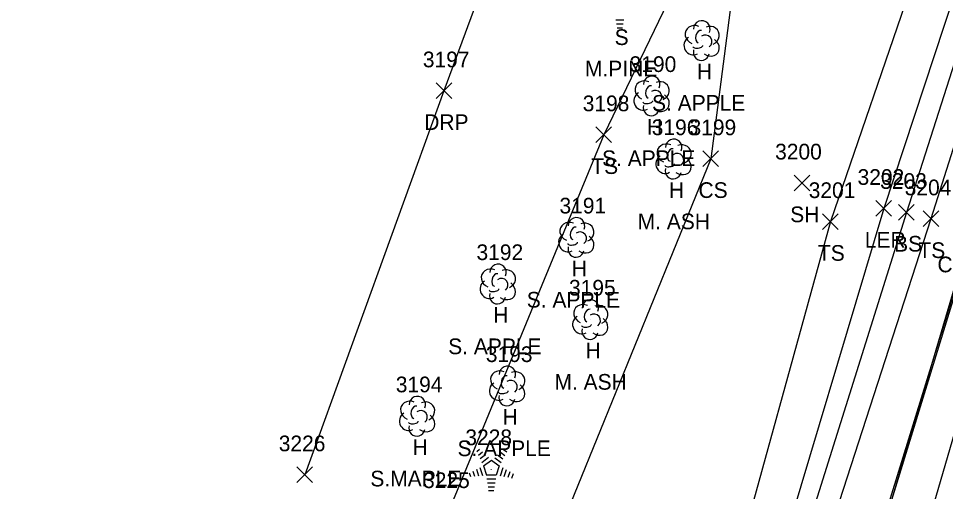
# Model space of a CAD drawing. Extents: x 1462089 to 1464015, y 730534 to 736144.
# Drawn here: x 1462931.1 to 1463049.3, y 732967.5 to 733027.8 of the extents above; entities that cross this region are included whole.
import ezdxf

# ---------------------------------------------------------------- set-up
doc = ezdxf.new("R2010")
doc.units = 0
for name, color, linetype in [('DCP', 7, 'Continuous'), ('L_A', 7, 'Continuous'), ('L_C', 7, 'Continuous'), ('L_I', 7, 'Continuous'), ('L_TIC', 7, 'Continuous'), ('LARO', 7, 'Continuous'), ('LELB', 7, 'Continuous'), ('LTC', 7, 'Continuous'), ('LTD', 7, 'Continuous'), ('PET', 7, 'Continuous'), ('PSP', 7, 'Continuous'), ('R_A', 7, 'Continuous'), ('R_I', 7, 'Continuous'), ('R_TIC', 7, 'Continuous'), ('RC', 7, 'Continuous'), ('RDP', 7, 'Continuous')]:
    doc.layers.add(name, color=color, linetype=linetype)

msp = doc.modelspace()

# ---------------------------------------------------------------- linework, layer by layer
at = {"layer": 'DCP'}
msp.add_lwpolyline([(1463113.91, 733208.21), (1463020.77, 732893.28)], dxfattribs=at)
at = {"layer": 'L_TIC'}
for points in [[(1463004.74, 733012.02), (1463006.74, 733014.02)], [(1463006.74, 733012.02), (1463004.74, 733014.02)], [(1463018.37, 733008.96), (1463020.37, 733010.96)], [(1463020.37, 733008.96), (1463018.37, 733010.96)], [(1463030.01, 733005.87), (1463032.01, 733007.87)], [(1463032.01, 733005.87), (1463030.01, 733007.87)], [(1463040.43, 733002.63), (1463042.43, 733004.63)], [(1463042.43, 733002.63), (1463040.43, 733004.63)], [(1463043.31, 733002.12), (1463045.31, 733004.12)], [(1463045.31, 733002.12), (1463043.31, 733004.12)], [(1463033.63, 733000.95), (1463035.63, 733002.95)], [(1463035.63, 733000.95), (1463033.63, 733002.95)], [(1463046.44, 733001.3), (1463048.44, 733003.3)], [(1463048.44, 733001.3), (1463046.44, 733003.3)]]:
    msp.add_lwpolyline(points, dxfattribs=at)
at = {"layer": 'LARO'}
msp.add_lwpolyline([(1463094.76, 733228.15), (1463096.03, 733229.51), (1463107.11, 733225.67), (1463106.44, 733220.79), (1463101.84, 733210.57), (1463094.26, 733183.58), (1463093.23, 733172.66), (1463084.96, 733140.71), (1463082.5, 733130.85), (1463075.1, 733107.4), (1463060.71, 733062.18), (1463041.43, 733003.63), (1463027.29, 732956.25), (1463020.7, 732939.68), (1463009.72, 732922.59), (1463000.8, 732913.83)], dxfattribs=at)
at = {"layer": 'LELB'}
for points in [[(1463108.71, 733226.1), (1463108.78, 733215.45), (1463107.91, 733210.67), (1463106.52, 733207.37), (1463097.65, 733182.34), (1463096.33, 733171.82), (1463062.97, 733061.46), (1463044.31, 733003.12), (1463029.33, 732955.28), (1463018.11, 732921.02), (1463012.52, 732895.45), (1463002.14, 732868.56), (1462989.94, 732828.37), (1462974.14, 732778.17), (1462962.05, 732738.86), (1462942.09, 732684.7)], [(1463108.71, 733226.1), (1463110.44, 733215.45), (1463109.61, 733208.14), (1463106.26, 733200.46), (1463099.08, 733171.5), (1463080.2, 733104.81), (1463066.07, 733061.12), (1463047.44, 733002.3), (1463031.89, 732954.26), (1463021.29, 732920.45), (1463016.04, 732893.81), (1463006.16, 732867.27), (1462993.39, 732826.96), (1462975.9, 732776.47), (1462964.59, 732738.3), (1462945.3, 732683.44)], [(1463035.34, 733085.44), (1463029.83, 733068.95), (1463024.96, 733052.89), (1463005.74, 733013.02), (1462985.96, 732964.97), (1462972.93, 732929.05)], [(1463055.63, 733063.21), (1463034.63, 733001.95), (1463021.17, 732953.09), (1463005.86, 732923.5), (1463000.8, 732913.83), (1462995.2, 732902.16), (1462991.68, 732870.51), (1462983.42, 732830.89), (1462971.91, 732797.99), (1462967.45, 732788.36), (1462962, 732775.43), (1462963.84, 732771.36), (1462954.15, 732748.13), (1462943.9, 732732.26), (1462943.46, 732721.31), (1462938.53, 732701.15), (1462919.19, 732660.62)], [(1463024.96, 733052.89), (1463019.37, 733009.96), (1463000.01, 732962.33), (1462984.86, 732926.01), (1462972.76, 732908.94), (1462960.37, 732884.47), (1462958.09, 732841.86), (1462948.33, 732829.18), (1462951.8, 732798.65), (1462940.09, 732777.68), (1462936.2, 732747.89), (1462927.88, 732723.49), (1462921.5, 732707.29), (1462904.86, 732665.94), (1462895.56, 732628.88), (1462895.22, 732616.02)]]:
    msp.add_lwpolyline(points, dxfattribs=at)
at = {"layer": 'LTC'}
for p, q in [((1463008.28, 733027.62), (1463007.29, 733027.62)), ((1463008.19, 733027.12), (1463007.36, 733027.12)), ((1463008.11, 733026.62), (1463007.43, 733026.62)), ((1462989.55, 732972.65), (1462989.9, 732972.91)), ((1462989.76, 732972.18), (1462990.29, 732972.57)), ((1462989.97, 732971.72), (1462990.67, 732972.23)), ((1462990.18, 732971.25), (1462991.05, 732971.89)), ((1462991.83, 732971.84), (1462992.64, 732971.25)), ((1462992.2, 732972.19), (1462992.88, 732971.7)), ((1462992.57, 732972.54), (1462993.12, 732972.14)), ((1462992.95, 732972.89), (1462993.37, 732972.58)), ((1462989.95, 732970.58), (1462990.28, 732969.56)), ((1462990.4, 732970.8), (1462991.41, 732971.53)), ((1462990.4, 732970.8), (1462990.79, 732969.6)), ((1462991.41, 732971.53), (1462992.41, 732970.81)), ((1462992.41, 732970.81), (1462992.02, 732969.6)), ((1462988.58, 732969.93), (1462988.73, 732969.46)), ((1462989.04, 732970.14), (1462989.25, 732969.49)), ((1462989.49, 732970.36), (1462989.76, 732969.53)), ((1462992.02, 732969.6), (1462990.79, 732969.6)), ((1462992.85, 732970.53), (1462992.51, 732969.5)), ((1462993.29, 732970.28), (1462993, 732969.4)), ((1462993.74, 732970.03), (1462993.5, 732969.3)), ((1462994.18, 732969.78), (1462993.99, 732969.21)), ((1462991.98, 732969.1), (1462990.84, 732969.1)), ((1462991.9, 732968.6), (1462990.91, 732968.6)), ((1462991.81, 732968.1), (1462990.98, 732968.1)), ((1462991.73, 732967.6), (1462991.05, 732967.6))]:
    msp.add_line(p, q, dxfattribs=at)
at = {"layer": 'LTD'}
for p, q in [((1463018.19, 733025.08), (1463018.19, 733025.08)), ((1463018.19, 733025.08), (1463018.19, 733025.08)), ((1463011.81, 733018.02), (1463011.81, 733018.02)), ((1463011.81, 733018.02), (1463011.81, 733018.02)), ((1463014.6, 733009.97), (1463014.6, 733009.97)), ((1463014.6, 733009.97), (1463014.6, 733009.97)), ((1463002.21, 732999.98), (1463002.21, 732999.98)), ((1463002.21, 732999.98), (1463002.21, 732999.98)), ((1462992.2, 732994.04), (1462992.2, 732994.04)), ((1462992.2, 732994.04), (1462992.2, 732994.04)), ((1463003.99, 732989.51), (1463003.99, 732989.51)), ((1463003.99, 732989.51), (1463003.99, 732989.51)), ((1462993.39, 732981.04), (1462993.39, 732981.04)), ((1462993.39, 732981.04), (1462993.39, 732981.04)), ((1462981.92, 732977.18), (1462981.92, 732977.18)), ((1462981.92, 732977.18), (1462981.92, 732977.18))]:
    msp.add_line(p, q, dxfattribs=at)
for centre in [(1463018.24, 733026.51), (1463011.86, 733019.45), (1463014.65, 733011.41), (1463002.26, 733001.41), (1462992.25, 732995.47), (1463004.04, 732990.94), (1462993.44, 732982.47), (1462981.96, 732978.62)]:
    msp.add_arc(centre, 1.05, 335.5272, 180.9563, dxfattribs=at)
for centre, major_axis, ratio, start_param, end_param in [((1463017.4, 733025.75), (1.21, -0.51), 0.895232, 1.570796, 4.712389), ((1463017.98, 733025.54), (-0.208, -0.792), 0.645439, 3.141593, 6.283185), ((1463019.23, 733025.66), (-1.14, -0.48), 0.949671, 1.570796, 4.712389), ((1463017.11, 733024.37), (0.58, -1.04), 0.959034, 3.141593, 6.283185), ((1463018.69, 733024.91), (-0.5, 0.667), 0.989748, 3.141593, 6.283185), ((1463019.19, 733024.25), (-1.09, 0.79), 0.841452, 1.570796, 4.712389), ((1463018.19, 733023.58), (0.26, 1.06), 0.942809, 1.570796, 4.712389), ((1463017.73, 733024.33), (-0.625, -0.083), 0.423636, 0, 3.141593), ((1463011.02, 733018.69), (1.21, -0.51), 0.895232, 1.570796, 4.712389), ((1463011.61, 733018.48), (-0.208, -0.792), 0.645439, 3.141593, 6.283185), ((1463012.86, 733018.6), (-1.14, -0.48), 0.949671, 1.570796, 4.712389), ((1463010.73, 733017.31), (0.58, -1.04), 0.959034, 3.141593, 6.283185), ((1463012.31, 733017.85), (-0.5, 0.667), 0.989748, 3.141593, 6.283185), ((1463012.81, 733017.19), (-1.09, 0.79), 0.841452, 1.570796, 4.712389), ((1463011.81, 733016.52), (0.26, 1.06), 0.942809, 1.570796, 4.712389), ((1463011.36, 733017.27), (-0.625, -0.083), 0.423636, 0, 3.141593), ((1463013.81, 733010.64), (1.21, -0.51), 0.895232, 1.570796, 4.712389), ((1463014.39, 733010.43), (-0.208, -0.792), 0.645439, 3.141593, 6.283185), ((1463015.64, 733010.56), (-1.14, -0.48), 0.949671, 1.570796, 4.712389), ((1463013.52, 733009.27), (0.58, -1.04), 0.959034, 3.141593, 6.283185), ((1463015.1, 733009.81), (-0.5, 0.667), 0.989748, 3.141593, 6.283185), ((1463015.6, 733009.14), (-1.09, 0.79), 0.841452, 1.570796, 4.712389), ((1463014.6, 733008.47), (0.26, 1.06), 0.942809, 1.570796, 4.712389), ((1463014.14, 733009.22), (-0.625, -0.083), 0.423636, 0, 3.141593), ((1463001.42, 733000.65), (1.21, -0.51), 0.895232, 1.570796, 4.712389), ((1463002.01, 733000.44), (-0.208, -0.792), 0.645439, 3.141593, 6.283185), ((1463003.26, 733000.56), (-1.14, -0.48), 0.949671, 1.570796, 4.712389), ((1463001.13, 732999.27), (0.58, -1.04), 0.959034, 3.141593, 6.283185), ((1463002.71, 732999.81), (-0.5, 0.667), 0.989748, 3.141593, 6.283185), ((1463001.76, 732999.23), (-0.625, -0.083), 0.423636, 0, 3.141593), ((1463003.21, 732999.15), (-1.09, 0.79), 0.841452, 1.570796, 4.712389), ((1463002.21, 732998.48), (0.26, 1.06), 0.942809, 1.570796, 4.712389), ((1462991.41, 732994.7), (1.21, -0.51), 0.895232, 1.570796, 4.712389), ((1462993.25, 732994.62), (-1.14, -0.48), 0.949671, 1.570796, 4.712389), ((1462991.12, 732993.33), (0.58, -1.04), 0.959034, 3.141593, 6.283185), ((1462992, 732994.49), (-0.208, -0.792), 0.645439, 3.141593, 6.283185), ((1462992.7, 732993.87), (-0.5, 0.667), 0.989748, 3.141593, 6.283185), ((1462991.75, 732993.29), (-0.625, -0.083), 0.423636, 0, 3.141593), ((1462993.2, 732993.2), (-1.09, 0.79), 0.841452, 1.570796, 4.712389), ((1462992.2, 732992.54), (0.26, 1.06), 0.942809, 1.570796, 4.712389), ((1463003.2, 732990.17), (1.21, -0.51), 0.895232, 1.570796, 4.712389), ((1463003.78, 732989.97), (-0.208, -0.792), 0.645439, 3.141593, 6.283185), ((1463005.03, 732990.09), (-1.14, -0.48), 0.949671, 1.570796, 4.712389), ((1463002.91, 732988.8), (0.58, -1.04), 0.959034, 3.141593, 6.283185), ((1463004.49, 732989.34), (-0.5, 0.667), 0.989748, 3.141593, 6.283185), ((1463004.99, 732988.67), (-1.09, 0.79), 0.841452, 1.570796, 4.712389), ((1463003.53, 732988.76), (-0.625, -0.083), 0.423636, 0, 3.141593), ((1463003.99, 732988.01), (0.26, 1.06), 0.942809, 1.570796, 4.712389), ((1462992.6, 732981.71), (1.21, -0.51), 0.895232, 1.570796, 4.712389), ((1462994.44, 732981.62), (-1.14, -0.48), 0.949671, 1.570796, 4.712389), ((1462992.31, 732980.33), (0.58, -1.04), 0.959034, 3.141593, 6.283185), ((1462993.19, 732981.5), (-0.208, -0.792), 0.645439, 3.141593, 6.283185), ((1462993.89, 732980.87), (-0.5, 0.667), 0.989748, 3.141593, 6.283185), ((1462992.94, 732980.29), (-0.625, -0.083), 0.423636, 0, 3.141593), ((1462994.39, 732980.21), (-1.09, 0.79), 0.841452, 1.570796, 4.712389), ((1462981.12, 732977.85), (1.21, -0.51), 0.895232, 1.570796, 4.712389), ((1462982.96, 732977.77), (-1.14, -0.48), 0.949671, 1.570796, 4.712389), ((1462993.39, 732979.54), (0.26, 1.06), 0.942809, 1.570796, 4.712389), ((1462981.71, 732977.64), (-0.208, -0.792), 0.645439, 3.141593, 6.283185), ((1462982.42, 732977.02), (-0.5, 0.667), 0.989748, 3.141593, 6.283185), ((1462980.83, 732976.47), (0.58, -1.04), 0.959034, 3.141593, 6.283185), ((1462981.46, 732976.43), (-0.625, -0.083), 0.423636, 0, 3.141593), ((1462982.92, 732976.35), (-1.09, 0.79), 0.841452, 1.570796, 4.712389), ((1462981.92, 732975.68), (0.26, 1.06), 0.942809, 1.570796, 4.712389)]:
    msp.add_ellipse(centre, major_axis=major_axis, ratio=ratio, start_param=start_param, end_param=end_param, dxfattribs=at)
at = {"layer": 'PET'}
msp.add_lwpolyline([(1463162.64, 733438.25), (1463155.29, 733389.19), (1463147.91, 733342.63), (1463141.51, 733306.47), (1463132.06, 733260.3), (1463123.36, 733223.56), (1463108.71, 733168.54), (1463089.87, 733101.56), (1463076.27, 733055.88), (1463056.85, 732997.04), (1463043.72, 732952), (1463030.35, 732910.94), (1463015.8, 732864.49), (1463002.53, 732823.32), (1462986.53, 732773.32), (1462974.36, 732735), (1462957.21, 732680.82)], dxfattribs=at)
at = {"layer": 'PSP'}
msp.add_lwpolyline([(1463155.47, 733437.1), (1463151.69, 733409.08), (1463149, 733391.93), (1463141.96, 733349.08), (1463135.18, 733308.49), (1463125.93, 733264.09), (1463122.72, 733251.49), (1463119.11, 733234.45), (1463113.24, 733211.25), (1463103.08, 733170.52), (1463084.78, 733103.69), (1463070.66, 733057.94), (1463052.86, 733000.45), (1463038.28, 732952.98), (1463025.31, 732912.14), (1463010.74, 732866.35), (1462997.43, 732825.46), (1462981.2, 732774.91), (1462968.73, 732736.5), (1462951.61, 732681.88)], dxfattribs=at)
at = {"layer": 'R_TIC'}
for points in [[(1462984.36, 733017.62), (1462986.36, 733019.62)], [(1462986.36, 733017.62), (1462984.36, 733019.62)], [(1462966.62, 732968.66), (1462968.62, 732970.66)], [(1462968.62, 732968.66), (1462966.62, 732970.66)]]:
    msp.add_lwpolyline(points, dxfattribs=at)
at = {"layer": 'RC'}
msp.add_lwpolyline([(1463111.2, 733221.62), (1463111.65, 733221.54), (1463112.56, 733218.83), (1463113.16, 733213.96), (1463112.93, 733211.4), (1463102.86, 733170.54), (1463084.32, 733103.79), (1463070.5, 733057.91), (1463052.69, 733000.48), (1463038.08, 732953.17), (1463025.2, 732912.25), (1463010.5, 732866.43), (1462997.21, 732825.5), (1462981.06, 732775.17), (1462968.5, 732736.53), (1462951.35, 732681.84)], dxfattribs=at)
at = {"layer": 'RDP'}
msp.add_lwpolyline([(1463003.46, 733112.43), (1463010.21, 733105.22), (1463012.77, 733098.29), (1463010.4, 733085.66), (1462993.36, 733040.36), (1462985.36, 733018.62), (1462967.62, 732969.66)], dxfattribs=at)

# ---------------------------------------------------------------- texts
at = {"layer": 'L_A'}
for s, p in [('S', (1463007.12, 733024.46)), ('H', (1463017.62, 733020.08)), ('H', (1463011.25, 733013.02)), ('TS', (1463004.15, 733008.02)), ('H', (1463014.03, 733004.97)), ('CS', (1463017.81, 733004.96)), ('SH', (1463029.5, 733001.87)), ('LER', (1463039.01, 732998.63)), ('BS', (1463042.75, 732998.12)), ('TS', (1463033.04, 732996.95)), ('TS', (1463045.85, 732997.3)), ('H', (1463001.65, 732994.98)), ('H', (1462991.64, 732989.04)), ('H', (1463003.42, 732984.51)), ('H', (1462992.83, 732976.04)), ('H', (1462981.35, 732972.18))]:
    msp.add_text(s, height=2, dxfattribs=at).set_placement(p)
at = {"layer": 'L_C'}
for s, p in [('M.PINE', (1463003.34, 733020.46)), ('S. APPLE', (1463011.89, 733016.08)), ('S. APPLE', (1463005.52, 733009.02)), ('M. ASH', (1463010.06, 733000.97)), ('S. APPLE', (1462995.92, 732990.98)), ('S. APPLE', (1462985.9, 732985.04)), ('M. ASH', (1462999.45, 732980.51)), ('S. APPLE', (1462987.09, 732972.04)), ('S.MAPLE', (1462975.98, 732968.18))]:
    msp.add_text(s, height=2, dxfattribs=at).set_placement(p)
at = {"layer": 'L_I'}
for s, p in [('3190', (1463009.03, 733021.02)), ('3198', (1463003.05, 733016.02)), ('3196', (1463011.85, 733012.97)), ('3199', (1463016.67, 733012.96)), ('3200', (1463027.58, 733009.87)), ('3202', (1463038.09, 733006.63)), ('3203', (1463040.97, 733006.12)), ('3204', (1463044.1, 733005.3)), ('3201', (1463031.86, 733004.95)), ('3191', (1463000.09, 733002.98)), ('3192', (1462989.51, 732997.04)), ('3195', (1463001.3, 732992.51)), ('3193', (1462990.7, 732984.04)), ('3194', (1462979.22, 732980.18)), ('3228', (1462988.09, 732973.44)), ('3225', (1462982.7, 732967.97))]:
    msp.add_text(s, height=2, dxfattribs=at).set_placement(p)
at = {"layer": 'LTC'}
msp.add_text('.', height=1.04, rotation=270, dxfattribs=at).set_placement((1462991.3, 732970.54))
at = {"layer": 'R_A'}
for s, p in [('DRP', (1462982.85, 733013.62)), ('CURBC', (1463048.27, 732995.48))]:
    msp.add_text(s, height=2, dxfattribs=at).set_placement(p)
at = {"layer": 'R_I'}
for s, p in [('3197', (1462982.67, 733021.62)), ('3226', (1462964.3, 732972.66))]:
    msp.add_text(s, height=2, dxfattribs=at).set_placement(p)

doc.saveas('drawing.dxf')
